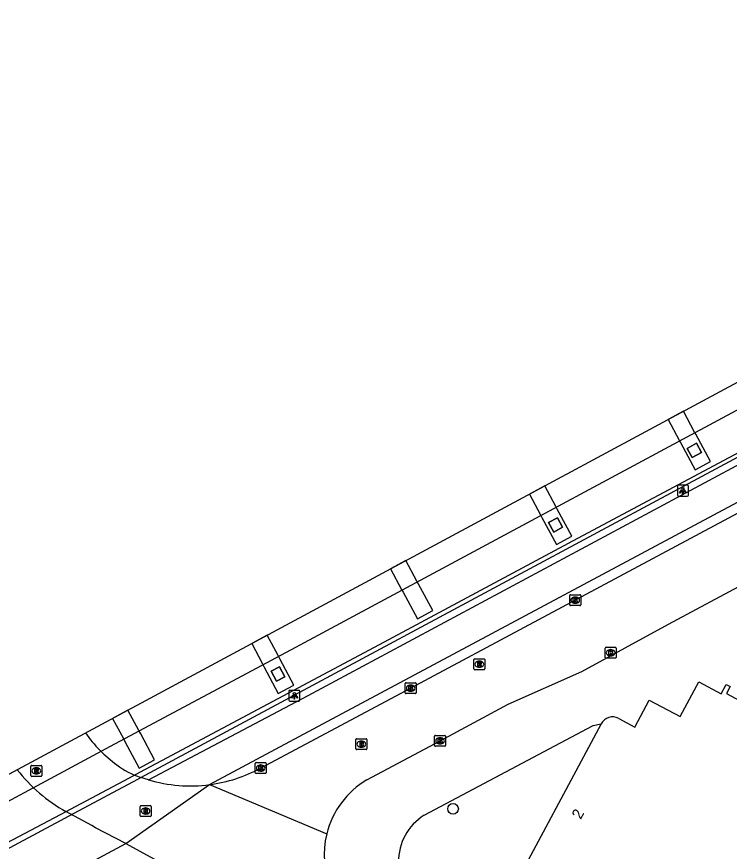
# Model space of a CAD drawing. Extents: x 159489 to 160304, y 383826 to 384530.
# Drawn here: x 159544.6 to 159609.7, y 384342.1 to 384418.4 of the extents above; entities that cross this region are included whole.
import ezdxf

# ---------------------------------------------------------------- set-up
doc = ezdxf.new("R2010")
doc.units = 0
for name, color, linetype in [('IMGEO_Boom', 7, 'Continuous'), ('IMGEO_Brandkraan', 7, 'Continuous'), ('IMGEO_Dek', 7, 'Continuous'), ('IMGEO_Fietspad_gesloten', 7, 'Continuous'), ('IMGEO_Kolk', 7, 'Continuous'), ('IMGEO_Lichtpunt', 7, 'Continuous'), ('IMGEO_Pand', 7, 'Continuous'), ('IMGEO_Pand_nummerreeks', 7, 'Continuous'), ('IMGEO_Pijler', 7, 'Continuous'), ('IMGEO_Rijbaan_lokaal_gesloten', 7, 'Continuous'), ('IMGEO_Rijbaan_regionaal_gesloten', 7, 'Continuous'), ('IMGEO_Rioolput', 7, 'Continuous'), ('IMGEO_Voetgangersgebied_gesloten', 7, 'Continuous'), ('IMGEO_Voetpad_open', 7, 'Continuous')]:
    doc.layers.add(name, color=color, linetype=linetype)

msp = doc.modelspace()

# ---------------------------------------------------------------- linework, layer by layer
at = {"layer": 'IMGEO_Boom'}
msp.add_circle((159584.446, 384346.009), 0.489, dxfattribs=at)
at = {"layer": 'IMGEO_Brandkraan'}
for p, q in [((159575.639, 384352.418), (159576.491, 384352.418)), ((159575.564, 384351.492), (159575.564, 384352.344)), ((159576.075, 384351.638), (159576.05, 384351.638)), ((159576.052, 384352.198), (159576.077, 384352.198)), ((159576.565, 384352.344), (159576.565, 384351.492)), ((159576.491, 384351.418), (159575.639, 384351.418))]:
    msp.add_line(p, q, dxfattribs=at)
for points in [[(159575.639, 384352.418), (159576.491, 384352.418)], [(159575.564, 384351.492), (159575.564, 384352.344)], [(159575.912, 384352.118), (159575.912, 384351.718), (159576.125, 384351.718)], [(159576.143, 384352.118), (159575.912, 384352.118)], [(159576.091, 384352.037), (159576.037, 384352.037), (159576.037, 384351.961)], [(159576.037, 384351.961), (159576.09, 384351.961)], [(159576.099, 384351.885), (159576.037, 384351.885), (159576.037, 384351.804)], [(159576.037, 384351.804), (159576.099, 384351.804)], [(159576.565, 384352.344), (159576.565, 384351.492)], [(159576.491, 384351.418), (159575.639, 384351.418)]]:
    msp.add_lwpolyline(points, dxfattribs=at)
for centre, radius, start, end in [((159575.641, 384352.342), 0.0765, 91.55205, 178.44795), ((159575.641, 384352.342), 0.0765, 91.55205, 178.44795), ((159576.489, 384352.342), 0.0765, 1.55205, 88.44795), ((159576.489, 384352.342), 0.0765, 1.55205, 88.44795), ((159576.092, 384351.999), 0.0379, 267.82845, 90.93552), ((159576.1, 384351.844), 0.0404, 269.87594, 90.50774), ((159576.131, 384351.969), 0.251, 268.66757, 293.53466), ((159576.147, 384351.973), 0.145, 59.4692, 91.53667), ((159576.172, 384352.02), 0.0922, 285.51372, 58.15012), ((159576.177, 384351.828), 0.105, 301.31148, 78.98903), ((159575.641, 384351.494), 0.0765, 181.55205, 268.44795), ((159575.641, 384351.494), 0.0765, 181.55205, 268.44795), ((159576.489, 384351.494), 0.0765, 271.55205, 358.44795), ((159576.489, 384351.494), 0.0765, 271.55205, 358.44795)]:
    msp.add_arc(centre, radius, start, end, dxfattribs=at)
for centre, major_axis, ratio, start_param, end_param in [((159576.051, 384351.918), (-0.387, 0.002), 0.722429, 4.712389, 7.853982), ((159576.076, 384351.918), (-0.39, 0.002), 0.717154, 1.570796, 4.712389)]:
    msp.add_ellipse(centre, major_axis=major_axis, ratio=ratio, start_param=start_param, end_param=end_param, dxfattribs=at)
at = {"layer": 'IMGEO_Dek'}
msp.add_lwpolyline([(159488.508, 384319.441), (159491.36, 384314.274), (159493.126, 384315.218), (159493.745, 384315.549), (159500.607, 384319.217), (159503.5, 384320.764), (159504.356, 384321.224), (159506.58, 384322.417), (159506.853, 384322.564), (159543.492, 384342.222), (159549.818, 384345.616), (159555.628, 384348.734), (159555.907, 384348.884), (159569.121, 384355.973), (159618.393, 384382.41), (159620.115, 384383.333), (159619.966, 384383.61), (159618.385, 384386.561), (159617.271, 384388.641)], close=True, dxfattribs=at)
at = {"layer": 'IMGEO_Fietspad_gesloten'}
for points in [[(159562.194, 384348.219), (159572.535, 384353.778), (159693.459, 384418.367)], [(159556.599, 384348.661), (159571.207, 384356.355), (159619.93, 384382.493)]]:
    msp.add_lwpolyline(points, dxfattribs=at)
at = {"layer": 'IMGEO_Kolk'}
for p, q in [((159595.114, 384364.644), (159595.114, 384365.496)), ((159595.189, 384365.57), (159596.041, 384365.57)), ((159596.115, 384365.496), (159596.115, 384364.644)), ((159595.625, 384364.79), (159595.6, 384364.79)), ((159595.602, 384365.35), (159595.627, 384365.35)), ((159596.041, 384364.57), (159595.189, 384364.57)), ((159598.358, 384359.845), (159598.358, 384360.697)), ((159598.433, 384360.771), (159599.285, 384360.771)), ((159598.846, 384360.551), (159598.871, 384360.551)), ((159599.359, 384360.697), (159599.359, 384359.845)), ((159599.285, 384359.771), (159598.433, 384359.771)), ((159598.869, 384359.991), (159598.844, 384359.991)), ((159580.08, 384356.605), (159580.08, 384357.457)), ((159580.155, 384357.531), (159581.007, 384357.531)), ((159580.568, 384357.311), (159580.593, 384357.311)), ((159581.081, 384357.457), (159581.081, 384356.605)), ((159581.007, 384356.531), (159580.155, 384356.531)), ((159580.591, 384356.751), (159580.566, 384356.751)), ((159582.759, 384351.794), (159582.759, 384352.646)), ((159582.834, 384352.72), (159583.686, 384352.72)), ((159583.247, 384352.5), (159583.272, 384352.5)), ((159583.76, 384352.646), (159583.76, 384351.794)), ((159583.686, 384351.72), (159582.834, 384351.72)), ((159583.27, 384351.94), (159583.245, 384351.94)), ((159566.366, 384349.31), (159566.366, 384350.162)), ((159566.441, 384350.236), (159567.293, 384350.236)), ((159567.367, 384350.162), (159567.367, 384349.31)), ((159566.877, 384349.456), (159566.852, 384349.456)), ((159566.854, 384350.016), (159566.879, 384350.016)), ((159567.293, 384349.236), (159566.441, 384349.236))]:
    msp.add_line(p, q, dxfattribs=at)
for points in [[(159595.114, 384364.644), (159595.114, 384365.496)], [(159595.189, 384365.57), (159596.041, 384365.57)], [(159596.115, 384365.496), (159596.115, 384364.644)], [(159595.435, 384365.27), (159595.558, 384365.27), (159595.558, 384365.119), (159595.688, 384365.27), (159595.852, 384365.27), (159595.706, 384365.119), (159595.859, 384364.87), (159595.707, 384364.87), (159595.622, 384365.034), (159595.558, 384364.967), (159595.558, 384364.87), (159595.435, 384364.87), (159595.435, 384365.27)], [(159596.041, 384364.57), (159595.189, 384364.57)], [(159598.358, 384359.845), (159598.358, 384360.697)], [(159598.433, 384360.771), (159599.285, 384360.771)], [(159598.679, 384360.471), (159598.802, 384360.471), (159598.802, 384360.32), (159598.932, 384360.471), (159599.096, 384360.471), (159598.95, 384360.32), (159599.103, 384360.071), (159598.951, 384360.071), (159598.866, 384360.235), (159598.802, 384360.168), (159598.802, 384360.071), (159598.679, 384360.071), (159598.679, 384360.471)], [(159599.359, 384360.697), (159599.359, 384359.845)], [(159599.285, 384359.771), (159598.433, 384359.771)], [(159580.08, 384356.605), (159580.08, 384357.457)], [(159580.155, 384357.531), (159581.007, 384357.531)], [(159580.401, 384357.231), (159580.524, 384357.231), (159580.524, 384357.08), (159580.654, 384357.231), (159580.818, 384357.231), (159580.672, 384357.08), (159580.825, 384356.831), (159580.673, 384356.831), (159580.588, 384356.995), (159580.524, 384356.928), (159580.524, 384356.831), (159580.401, 384356.831), (159580.401, 384357.231)], [(159581.081, 384357.457), (159581.081, 384356.605)], [(159581.007, 384356.531), (159580.155, 384356.531)], [(159582.759, 384351.794), (159582.759, 384352.646)], [(159582.834, 384352.72), (159583.686, 384352.72)], [(159583.08, 384352.42), (159583.203, 384352.42), (159583.203, 384352.269), (159583.333, 384352.42), (159583.497, 384352.42), (159583.351, 384352.269), (159583.504, 384352.02), (159583.352, 384352.02), (159583.267, 384352.184), (159583.203, 384352.117), (159583.203, 384352.02), (159583.08, 384352.02), (159583.08, 384352.42)], [(159583.76, 384352.646), (159583.76, 384351.794)], [(159583.686, 384351.72), (159582.834, 384351.72)], [(159566.366, 384349.31), (159566.366, 384350.162)], [(159566.441, 384350.236), (159567.293, 384350.236)], [(159567.367, 384350.162), (159567.367, 384349.31)], [(159566.687, 384349.936), (159566.81, 384349.936), (159566.81, 384349.785), (159566.94, 384349.936), (159567.104, 384349.936), (159566.958, 384349.785), (159567.111, 384349.536), (159566.959, 384349.536), (159566.874, 384349.7), (159566.81, 384349.633), (159566.81, 384349.536), (159566.687, 384349.536), (159566.687, 384349.936)], [(159567.293, 384349.236), (159566.441, 384349.236)]]:
    msp.add_lwpolyline(points, dxfattribs=at)
for centre, start, end in [((159595.191, 384365.494), 91.55205, 178.44795), ((159595.191, 384365.494), 91.55205, 178.44795), ((159596.039, 384365.494), 1.55205, 88.44795), ((159596.039, 384365.494), 1.55205, 88.44795), ((159595.191, 384364.646), 181.55205, 268.44795), ((159595.191, 384364.646), 181.55205, 268.44795), ((159596.039, 384364.646), 271.55205, 358.44795), ((159596.039, 384364.646), 271.55205, 358.44795), ((159598.435, 384360.695), 91.55205, 178.44795), ((159598.435, 384360.695), 91.55205, 178.44795), ((159599.283, 384360.695), 1.55205, 88.44795), ((159599.283, 384360.695), 1.55205, 88.44795), ((159598.435, 384359.847), 181.55205, 268.44795), ((159598.435, 384359.847), 181.55205, 268.44795), ((159599.283, 384359.847), 271.55205, 358.44795), ((159599.283, 384359.847), 271.55205, 358.44795), ((159580.157, 384357.455), 91.55205, 178.44795), ((159580.157, 384357.455), 91.55205, 178.44795), ((159581.005, 384357.455), 1.55205, 88.44795), ((159581.005, 384357.455), 1.55205, 88.44795), ((159580.157, 384356.607), 181.55205, 268.44795), ((159580.157, 384356.607), 181.55205, 268.44795), ((159581.005, 384356.607), 271.55205, 358.44795), ((159581.005, 384356.607), 271.55205, 358.44795), ((159582.836, 384352.644), 91.55205, 178.44795), ((159582.836, 384352.644), 91.55205, 178.44795), ((159583.684, 384352.644), 1.55205, 88.44795), ((159583.684, 384352.644), 1.55205, 88.44795), ((159582.836, 384351.796), 181.55205, 268.44795), ((159582.836, 384351.796), 181.55205, 268.44795), ((159583.684, 384351.796), 271.55205, 358.44795), ((159583.684, 384351.796), 271.55205, 358.44795), ((159566.443, 384350.16), 91.55205, 178.44795), ((159566.443, 384350.16), 91.55205, 178.44795), ((159567.291, 384350.16), 1.55205, 88.44795), ((159567.291, 384350.16), 1.55205, 88.44795), ((159566.443, 384349.312), 181.55205, 268.44795), ((159566.443, 384349.312), 181.55205, 268.44795), ((159567.291, 384349.312), 271.55205, 358.44795), ((159567.291, 384349.312), 271.55205, 358.44795)]:
    msp.add_arc(centre, 0.0765, start, end, dxfattribs=at)
for centre, major_axis, ratio, start_param, end_param in [((159595.601, 384365.07), (-0.387, 0.002), 0.722429, 4.712389, 7.853982), ((159595.626, 384365.07), (-0.39, 0.002), 0.717154, 1.570796, 4.712389), ((159598.845, 384360.271), (-0.387, 0.002), 0.722429, 4.712389, 7.853982), ((159598.87, 384360.271), (-0.39, 0.002), 0.717154, 1.570796, 4.712389), ((159580.567, 384357.031), (-0.387, 0.002), 0.722429, 4.712389, 7.853982), ((159580.592, 384357.031), (-0.39, 0.002), 0.717154, 1.570796, 4.712389), ((159583.246, 384352.22), (-0.387, 0.002), 0.722429, 4.712389, 7.853982), ((159583.271, 384352.22), (-0.39, 0.002), 0.717154, 1.570796, 4.712389), ((159566.853, 384349.736), (-0.387, 0.002), 0.722429, 4.712389, 7.853982), ((159566.878, 384349.736), (-0.39, 0.002), 0.717154, 1.570796, 4.712389)]:
    msp.add_ellipse(centre, major_axis=major_axis, ratio=ratio, start_param=start_param, end_param=end_param, dxfattribs=at)
at = {"layer": 'IMGEO_Lichtpunt'}
for p, q in [((159604.96, 384375.471), (159604.96, 384374.664)), ((159604.96, 384375.471), (159604.96, 384374.664)), ((159605.862, 384375.566), (159605.054, 384375.566)), ((159605.862, 384375.566), (159605.054, 384375.566)), ((159605.956, 384374.664), (159605.956, 384375.471)), ((159605.956, 384374.664), (159605.956, 384375.471)), ((159605.054, 384374.57), (159605.862, 384374.57)), ((159605.054, 384374.57), (159605.862, 384374.57)), ((159569.445, 384356.737), (159569.445, 384355.93)), ((159569.445, 384356.737), (159569.445, 384355.93)), ((159570.347, 384356.832), (159569.539, 384356.832)), ((159570.347, 384356.832), (159569.539, 384356.832)), ((159570.441, 384355.93), (159570.441, 384356.737)), ((159570.441, 384355.93), (159570.441, 384356.737)), ((159569.539, 384355.836), (159570.347, 384355.836)), ((159569.539, 384355.836), (159570.347, 384355.836))]:
    msp.add_line(p, q, dxfattribs=at)
for points in [[(159605.334, 384375.135), (159605.373, 384375.107), (159605.185, 384374.845), (159605.147, 384374.872), (159605.334, 384375.135)], [(159605.436, 384375.087), (159605.483, 384375.087), (159605.483, 384374.765), (159605.436, 384374.765), (159605.436, 384375.087)], [(159605.546, 384375.107), (159605.584, 384375.134), (159605.771, 384374.872), (159605.732, 384374.844), (159605.546, 384375.107)], [(159569.819, 384356.401), (159569.858, 384356.373), (159569.67, 384356.111), (159569.632, 384356.138), (159569.819, 384356.401)], [(159569.921, 384356.353), (159569.968, 384356.353), (159569.968, 384356.031), (159569.921, 384356.031), (159569.921, 384356.353)], [(159570.031, 384356.373), (159570.069, 384356.4), (159570.256, 384356.138), (159570.217, 384356.11), (159570.031, 384356.373)]]:
    msp.add_lwpolyline(points, dxfattribs=at)
for centre in [(159605.459, 384375.269), (159569.944, 384356.535)]:
    msp.add_circle(centre, 0.0994, dxfattribs=at)
for centre, start, end in [((159605.054, 384375.471), 90, 180), ((159605.054, 384375.471), 90, 180), ((159605.862, 384375.471), 0, 90), ((159605.862, 384375.471), 0, 90), ((159605.054, 384374.664), 180, 270), ((159605.054, 384374.664), 180, 270), ((159605.862, 384374.664), 270, 0), ((159605.862, 384374.664), 270, 360), ((159569.539, 384356.737), 90, 180), ((159569.539, 384356.737), 90, 180), ((159570.347, 384356.737), 0, 90), ((159570.347, 384356.737), 0, 90), ((159569.539, 384355.93), 180, 270), ((159569.539, 384355.93), 180, 270), ((159570.347, 384355.93), 270, 0), ((159570.347, 384355.93), 270, 360)]:
    msp.add_arc(centre, 0.0946, start, end, dxfattribs=at)
at = {"layer": 'IMGEO_Pand'}
for points in [[(159599.589, 384354.271), (159601.071, 384353.466), (159602.39, 384355.944), (159605.205, 384354.438), (159606.901, 384357.605), (159608.96, 384356.518), (159609.409, 384357.376), (159609.794, 384357.17), (159609.456, 384356.538), (159612.282, 384355.014), (159617.084, 384363.924)], [(159597.986, 384353.77), (159589.25, 384337.446)]]:
    msp.add_lwpolyline(points, dxfattribs=at)
msp.add_arc((159599.038, 384353.22), 1.187, 62.30865, 152.40347, dxfattribs=at)
at = {"layer": 'IMGEO_Pijler'}
for points in [[(159604.103, 384381.564), (159605.122, 384379.672), (159605.233, 384379.466), (159606.578, 384376.969), (159607.987, 384377.728), (159606.642, 384380.225), (159606.533, 384380.428), (159605.513, 384382.322)], [(159606.32, 384378.107), (159605.858, 384378.938), (159606.689, 384379.399), (159607.15, 384378.569)], [(159606.32, 384378.107), (159607.15, 384378.569), (159606.689, 384379.399), (159605.858, 384378.938)], [(159592.84, 384375.511), (159591.422, 384374.749), (159592.433, 384372.865), (159592.56, 384372.628), (159593.894, 384370.142), (159595.312, 384370.903), (159593.976, 384373.392), (159593.851, 384373.625)], [(159593.661, 384371.296), (159593.186, 384372.158), (159593.983, 384372.597), (159594.458, 384371.735)], [(159593.661, 384371.296), (159594.458, 384371.735), (159593.983, 384372.597), (159593.186, 384372.158)], [(159580.139, 384368.685), (159578.728, 384367.927), (159579.736, 384366.053), (159579.879, 384365.787), (159581.186, 384363.356), (159582.596, 384364.114), (159581.288, 384366.547), (159581.147, 384366.81)], [(159567.46, 384361.871), (159566.042, 384361.11), (159567.033, 384359.244), (159567.193, 384358.943), (159568.462, 384356.553), (159569.883, 384357.308), (159568.609, 384359.707), (159568.451, 384360.005)], [(159568.313, 384357.665), (159567.826, 384358.585), (159568.568, 384358.978), (159569.056, 384358.058)], [(159568.313, 384357.665), (159569.056, 384358.058), (159568.568, 384358.978), (159567.826, 384358.585)], [(159554.731, 384355.031), (159553.324, 384354.274), (159554.31, 384352.425), (159554.489, 384352.089), (159555.748, 384349.728), (159557.158, 384350.479), (159555.895, 384352.848), (159555.718, 384353.18)]]:
    msp.add_lwpolyline(points, close=True, dxfattribs=at)
at = {"layer": 'IMGEO_Rijbaan_lokaal_gesloten'}
for points in [[(159693.863, 384417.603), (159580.529, 384357.003), (159566.867, 384349.736)], [(159576.58, 384348.662), (159583.26, 384352.22), (159589.5, 384355.56), (159596.233, 384358.541), (159604.138, 384362.877), (159611.421, 384366.774)], [(159556.599, 384348.661), (159555.907, 384348.884)], [(159554.539, 384342.832), (159562.194, 384348.219)], [(159562.194, 384348.219), (159572.9, 384343.713)], [(159554.539, 384342.832), (159551.757, 384344.289), (159551.418, 384344.475), (159549.06, 384345.769)], [(159554.539, 384342.832), (159562.552, 384338.47), (159578.411, 384329.953)]]:
    msp.add_lwpolyline(points, dxfattribs=at)
for centre, radius, start, end in [((159561.358, 384360.478), 12.942, 215.62923, 233.79325), ((159556.06, 384358.461), 14.494, 217.75699, 241.12323), ((159558.02, 384355.579), 7.02, 232.15419, 252.48168), ((159560.433, 384361.598), 13.494, 277.49638, 298.47368), ((159560.436, 384361.602), 13.497, 253.48337, 277.48276), ((159580.623, 384341.813), 7.953, 120.55409, 166.17806), ((159580.622, 384341.814), 7.952, 166.1799, 238.09513)]:
    msp.add_arc(centre, radius, start, end, dxfattribs=at)
at = {"layer": 'IMGEO_Rijbaan_regionaal_gesloten'}
for points in [[(159618.33, 384386.664), (159613.14, 384383.883), (159570.032, 384360.747), (159553.091, 384351.689), (159516.94, 384332.242), (159499.262, 384322.788), (159489.531, 384317.589)], [(159491.161, 384314.634), (159491.806, 384314.98), (159492.28, 384315.238), (159494.171, 384316.27), (159500, 384319.451), (159500.374, 384319.655), (159500.418, 384319.679), (159502.428, 384320.753), (159503.648, 384321.406), (159506.346, 384322.849), (159506.618, 384322.994), (159515.883, 384327.948), (159524.772, 384332.69), (159543.262, 384342.679), (159543.661, 384342.895), (159548.566, 384345.506), (159549.006, 384345.74), (159555.254, 384349.067), (159555.814, 384349.365), (159557.818, 384350.431), (159568.472, 384356.103), (159577.717, 384361.023), (159595.84, 384370.739), (159616.597, 384381.793)]]:
    msp.add_lwpolyline(points, dxfattribs=at)
at = {"layer": 'IMGEO_Rioolput'}
for p, q in [((159586.352, 384358.789), (159586.352, 384359.641)), ((159586.427, 384359.715), (159587.279, 384359.715)), ((159586.84, 384359.495), (159586.865, 384359.495)), ((159587.353, 384359.641), (159587.353, 384358.789)), ((159587.279, 384358.715), (159586.427, 384358.715)), ((159586.863, 384358.935), (159586.838, 384358.935)), ((159545.858, 384349.05), (159545.858, 384349.902)), ((159545.933, 384349.976), (159546.785, 384349.976)), ((159546.346, 384349.756), (159546.371, 384349.756)), ((159546.859, 384349.902), (159546.859, 384349.05)), ((159546.785, 384348.976), (159545.933, 384348.976)), ((159546.369, 384349.196), (159546.344, 384349.196)), ((159555.917, 384346.311), (159556.769, 384346.311)), ((159555.842, 384345.385), (159555.842, 384346.237)), ((159556.353, 384345.531), (159556.328, 384345.531)), ((159556.33, 384346.091), (159556.355, 384346.091)), ((159556.843, 384346.237), (159556.843, 384345.385)), ((159556.769, 384345.311), (159555.917, 384345.311))]:
    msp.add_line(p, q, dxfattribs=at)
for points in [[(159586.352, 384358.789), (159586.352, 384359.641)], [(159586.427, 384359.715), (159587.279, 384359.715)], [(159586.941, 384359.413), (159586.689, 384359.415), (159586.689, 384359.015)], [(159586.867, 384359.334), (159586.813, 384359.334), (159586.813, 384359.253)], [(159586.813, 384359.253), (159586.865, 384359.253)], [(159587.353, 384359.641), (159587.353, 384358.789)], [(159587.279, 384358.715), (159586.427, 384358.715)], [(159586.689, 384359.015), (159586.813, 384359.015), (159586.813, 384359.177), (159586.824, 384359.177)], [(159586.871, 384359.148), (159586.942, 384359.015), (159587.082, 384359.015), (159587.017, 384359.141)], [(159545.858, 384349.05), (159545.858, 384349.902)], [(159545.933, 384349.976), (159546.785, 384349.976)], [(159546.447, 384349.674), (159546.195, 384349.676), (159546.195, 384349.276)], [(159546.195, 384349.276), (159546.319, 384349.276), (159546.319, 384349.438), (159546.33, 384349.438)], [(159546.373, 384349.595), (159546.319, 384349.595), (159546.319, 384349.514)], [(159546.319, 384349.514), (159546.371, 384349.514)], [(159546.377, 384349.409), (159546.448, 384349.276), (159546.588, 384349.276), (159546.523, 384349.402)], [(159546.859, 384349.902), (159546.859, 384349.05)], [(159546.785, 384348.976), (159545.933, 384348.976)], [(159555.917, 384346.311), (159556.769, 384346.311)], [(159555.842, 384345.385), (159555.842, 384346.237)], [(159556.431, 384346.009), (159556.179, 384346.011), (159556.179, 384345.611)], [(159556.179, 384345.611), (159556.303, 384345.611), (159556.303, 384345.773), (159556.314, 384345.773)], [(159556.357, 384345.93), (159556.303, 384345.93), (159556.303, 384345.849)], [(159556.303, 384345.849), (159556.355, 384345.849)], [(159556.361, 384345.744), (159556.432, 384345.611), (159556.572, 384345.611), (159556.507, 384345.737)], [(159556.843, 384346.237), (159556.843, 384345.385)], [(159556.769, 384345.311), (159555.917, 384345.311)]]:
    msp.add_lwpolyline(points, dxfattribs=at)
for centre, radius, start, end in [((159586.429, 384359.639), 0.0765, 91.55205, 178.44795), ((159586.429, 384359.639), 0.0765, 91.55205, 178.44795), ((159586.849, 384359.442), 0.19, 274.7715, 282.96867), ((159586.873, 384359.238), 0.0964, 77.00612, 93.18647), ((159586.887, 384359.295), 0.0378, 276.66336, 79.67722), ((159586.94, 384359.303), 0.109, 350.36119, 89.41601), ((159586.938, 384359.303), 0.112, 277.58423, 350.98172), ((159587.277, 384359.639), 0.0765, 1.55205, 88.44795), ((159587.277, 384359.639), 0.0765, 1.55205, 88.44795), ((159586.429, 384358.791), 0.0765, 181.55205, 268.44795), ((159586.429, 384358.791), 0.0765, 181.55205, 268.44795), ((159586.823, 384359.124), 0.0533, 26.02933, 88.69889), ((159586.922, 384359.088), 0.108, 29.51342, 73.79051), ((159587.277, 384358.791), 0.0765, 271.55205, 358.44795), ((159587.277, 384358.791), 0.0765, 271.55205, 358.44795), ((159545.935, 384349.9), 0.0765, 91.55205, 178.44795), ((159545.935, 384349.9), 0.0765, 91.55205, 178.44795), ((159546.329, 384349.385), 0.0533, 26.02933, 88.69889), ((159546.355, 384349.703), 0.19, 274.7715, 282.96867), ((159546.379, 384349.499), 0.0964, 77.00612, 93.18647), ((159546.393, 384349.556), 0.0378, 276.66336, 79.67722), ((159546.446, 384349.564), 0.109, 350.36119, 89.41601), ((159546.444, 384349.564), 0.112, 277.58423, 350.98172), ((159546.428, 384349.349), 0.108, 29.51342, 73.79051), ((159546.783, 384349.9), 0.0765, 1.55205, 88.44795), ((159546.783, 384349.9), 0.0765, 1.55205, 88.44795), ((159545.935, 384349.052), 0.0765, 181.55205, 268.44795), ((159545.935, 384349.052), 0.0765, 181.55205, 268.44795), ((159546.783, 384349.052), 0.0765, 271.55205, 358.44795), ((159546.783, 384349.052), 0.0765, 271.55205, 358.44795), ((159555.919, 384346.235), 0.0765, 91.55205, 178.44795), ((159555.919, 384346.235), 0.0765, 91.55205, 178.44795), ((159556.767, 384346.235), 0.0765, 1.55205, 88.44795), ((159556.767, 384346.235), 0.0765, 1.55205, 88.44795), ((159556.313, 384345.72), 0.0533, 26.02933, 88.69889), ((159556.339, 384346.038), 0.19, 274.7715, 282.96867), ((159556.363, 384345.834), 0.0964, 77.00612, 93.18647), ((159556.377, 384345.891), 0.0378, 276.66336, 79.67722), ((159556.43, 384345.899), 0.109, 350.36119, 89.41601), ((159556.428, 384345.899), 0.112, 277.58423, 350.98172), ((159556.412, 384345.684), 0.108, 29.51342, 73.79051), ((159555.919, 384345.387), 0.0765, 181.55205, 268.44795), ((159555.919, 384345.387), 0.0765, 181.55205, 268.44795), ((159556.767, 384345.387), 0.0765, 271.55205, 358.44795), ((159556.767, 384345.387), 0.0765, 271.55205, 358.44795)]:
    msp.add_arc(centre, radius, start, end, dxfattribs=at)
for centre, major_axis, ratio, start_param, end_param in [((159586.839, 384359.215), (-0.387, 0.002), 0.722429, 4.712389, 7.853982), ((159586.864, 384359.215), (-0.39, 0.002), 0.717154, 1.570796, 4.712389), ((159546.345, 384349.476), (-0.387, 0.002), 0.722429, 4.712389, 7.853982), ((159546.37, 384349.476), (-0.39, 0.002), 0.717154, 1.570796, 4.712389), ((159556.329, 384345.811), (-0.387, 0.002), 0.722429, 4.712389, 7.853982), ((159556.354, 384345.811), (-0.39, 0.002), 0.717154, 1.570796, 4.712389)]:
    msp.add_ellipse(centre, major_axis=major_axis, ratio=ratio, start_param=start_param, end_param=end_param, dxfattribs=at)
at = {"layer": 'IMGEO_Voetgangersgebied_gesloten'}
msp.add_lwpolyline([(159541.465, 384335.842), (159554.539, 384342.832)], dxfattribs=at)
at = {"layer": 'IMGEO_Voetpad_open'}
msp.add_lwpolyline([(159581.812, 384345.424), (159597.261, 384353.625), (159597.986, 384353.77)], dxfattribs=at)
msp.add_arc((159584.432, 384341.193), 4.976, 121.76861, 239.74952, dxfattribs=at)

# ---------------------------------------------------------------- texts
at = {"layer": 'IMGEO_Pand_nummerreeks'}
msp.add_text('2', height=1, rotation=61.84596, dxfattribs=at).set_placement((159596.12, 384344.984))

doc.saveas('drawing.dxf')
